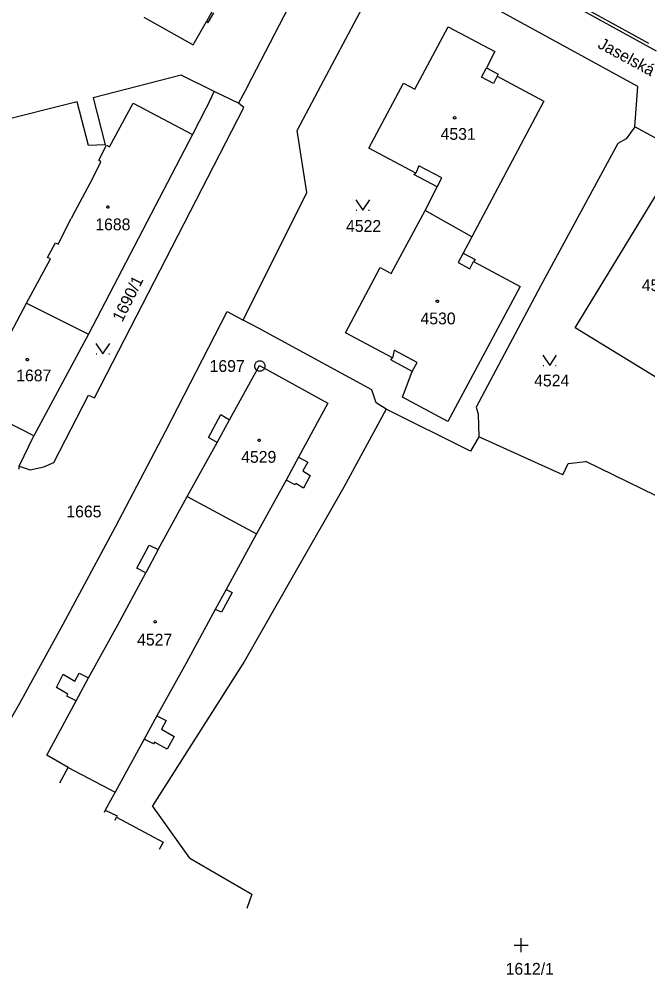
# Model space of a CAD drawing. Extents: x -528274 to -527531, y -1079304 to -1078580.
# Drawn here: x -527954.6 to -527864, y -1079223 to -1079085.4 of the extents above; entities that cross this region are included whole.
import ezdxf

# ---------------------------------------------------------------- set-up
doc = ezdxf.new("R2010")
doc.units = 0
doc.layers.add('katastrální mapa', color=7, linetype='Continuous')

msp = doc.modelspace()

# ---------------------------------------------------------------- linework, layer by layer
at = {"layer": 'katastrální mapa'}
for p, q in [((-527890.1, -1079074.91), (-527862.81, -1079089.91)), ((-527863.87, -1079088.86), (-527884.84, -1079077.28)), ((-527865.43, -1079095.09), (-527895.13, -1079078.8)), ((-527921.73, -1079095.17), (-527915.12, -1079082.34)), ((-527910.67, -1079094.17), (-527903.98, -1079081.56)), ((-527936.63, -1079085.07), (-527929.52, -1079089.06)), ((-527926.81, -1079084.3), (-527927.6, -1079085.69)), ((-527927.35, -1079085.83), (-527926.56, -1079084.44)), ((-527929.52, -1079089.06), (-527927.6, -1079085.69)), ((-527927.6, -1079085.69), (-527927.35, -1079085.83)), ((-527897.58, -1079095.45), (-527892.78, -1079086.47)), ((-527892.78, -1079086.47), (-527886.03, -1079090.03)), ((-527886.03, -1079090.03), (-527887.26, -1079092.37)), ((-527887.97, -1079093.71), (-527887.26, -1079092.37)), ((-527887.26, -1079092.37), (-527885.55, -1079093.28)), ((-527931.27, -1079093.45), (-527943.94, -1079096.7)), ((-527926.48, -1079095.78), (-527931.27, -1079093.45)), ((-527886.26, -1079094.62), (-527887.97, -1079093.71)), ((-527885.71, -1079093.59), (-527886.26, -1079094.62)), ((-527885.55, -1079093.28), (-527885.71, -1079093.59)), ((-527885.71, -1079093.59), (-527878.97, -1079097.19)), ((-527921.73, -1079095.17), (-527922.99, -1079097.47)), ((-527914.52, -1079101.41), (-527910.67, -1079094.17)), ((-527904.2, -1079103.97), (-527899.19, -1079094.59)), ((-527899.19, -1079094.59), (-527897.58, -1079095.45)), ((-527865.87, -1079100.87), (-527865.43, -1079095.09)), ((-527927.17, -1079097.21), (-527926.48, -1079095.78)), ((-527922.99, -1079097.47), (-527926.48, -1079095.78)), ((-527946.23, -1079097.26), (-527961.15, -1079101.04)), ((-527944.61, -1079103.58), (-527946.23, -1079097.26)), ((-527943.94, -1079096.7), (-527942.22, -1079103.47)), ((-527941.59, -1079103.74), (-527938.18, -1079097.48)), ((-527938.18, -1079097.48), (-527929.6, -1079101.99)), ((-527927.17, -1079097.21), (-527927.69, -1079098.23)), ((-527922.2, -1079098.11), (-527922.99, -1079097.47)), ((-527878.97, -1079097.19), (-527889.36, -1079116.7)), ((-527943.73, -1079139.94), (-527922.2, -1079098.11)), ((-527927.69, -1079098.23), (-527929.6, -1079101.99)), ((-527929.6, -1079101.99), (-527944.61, -1079130.76)), ((-527913.15, -1079110.35), (-527914.52, -1079101.41)), ((-527865.87, -1079100.87), (-527867.1, -1079102.61)), ((-527847.48, -1079111.01), (-527865.87, -1079100.87)), ((-527942.22, -1079103.47), (-527944.61, -1079103.58)), ((-527868.34, -1079103.27), (-527879.49, -1079123.84)), ((-527867.1, -1079102.61), (-527868.34, -1079103.27)), ((-527943.11, -1079105.68), (-527942.01, -1079103.52)), ((-527942.01, -1079103.52), (-527941.59, -1079103.74)), ((-527897.45, -1079107.57), (-527904.2, -1079103.97)), ((-527944, -1079108.28), (-527942.82, -1079105.92)), ((-527942.82, -1079105.92), (-527943.11, -1079105.68)), ((-527897.74, -1079107.75), (-527897.45, -1079107.57)), ((-527897.01, -1079106.5), (-527897.45, -1079107.57)), ((-527893.67, -1079108.24), (-527897.01, -1079106.5)), ((-527946.91, -1079113.74), (-527944, -1079108.28)), ((-527894.34, -1079109.52), (-527897.74, -1079107.75)), ((-527894.34, -1079109.52), (-527893.67, -1079108.24)), ((-527922.31, -1079128.71), (-527913.15, -1079110.35)), ((-527896.11, -1079112.93), (-527894.34, -1079109.52)), ((-527874.49, -1079129.82), (-527861.78, -1079109.06)), ((-527906.03, -1079112.9), (-527905.93, -1079112.9)), ((-527904.23, -1079112.9), (-527904.13, -1079112.9)), ((-527900.98, -1079122), (-527896.11, -1079112.93)), ((-527889.36, -1079116.7), (-527896.11, -1079112.93)), ((-527948.99, -1079117.76), (-527947.08, -1079114.07)), ((-527946.91, -1079113.74), (-527947.08, -1079114.07)), ((-527889.53, -1079117.02), (-527890.6, -1079119.07)), ((-527889.36, -1079116.7), (-527889.53, -1079117.02)), ((-527950.5, -1079119.68), (-527949.38, -1079117.57)), ((-527949.38, -1079117.57), (-527948.99, -1079117.76)), ((-527953.53, -1079126.27), (-527950.1, -1079119.89)), ((-527950.1, -1079119.89), (-527950.5, -1079119.68)), ((-527890.6, -1079119.07), (-527891.35, -1079120.43)), ((-527890.6, -1079119.07), (-527888.9, -1079119.98)), ((-527888.9, -1079119.98), (-527889.12, -1079120.28)), ((-527907.56, -1079130.55), (-527902.56, -1079121.16)), ((-527902.56, -1079121.16), (-527900.98, -1079122)), ((-527891.35, -1079120.43), (-527889.65, -1079121.33)), ((-527889.65, -1079121.33), (-527889.12, -1079120.28)), ((-527889.12, -1079120.28), (-527882.38, -1079123.89)), ((-527882.38, -1079123.89), (-527892.81, -1079143.32)), ((-527879.49, -1079123.84), (-527888.76, -1079141.24)), ((-527956.76, -1079132.39), (-527953.53, -1079126.27)), ((-527953.53, -1079126.27), (-527944.61, -1079130.76)), ((-527933.53, -1079144.79), (-527924.62, -1079127.48)), ((-527924.62, -1079127.48), (-527922.31, -1079128.71)), ((-527920.12, -1079129.88), (-527922.31, -1079128.71)), ((-527944.61, -1079130.76), (-527952.47, -1079145.37)), ((-527903.76, -1079138.76), (-527920.12, -1079129.88)), ((-527900.81, -1079134.15), (-527907.56, -1079130.55)), ((-527862.92, -1079136.88), (-527874.49, -1079129.82)), ((-527943.49, -1079133.57), (-527943.39, -1079133.57)), ((-527941.69, -1079133.57), (-527941.59, -1079133.57)), ((-527900.55, -1079133.03), (-527900.81, -1079134.15)), ((-527897.25, -1079134.82), (-527900.55, -1079133.03)), ((-527901.04, -1079134.45), (-527900.81, -1079134.15)), ((-527897.96, -1079136.12), (-527901.04, -1079134.45)), ((-527897.96, -1079136.12), (-527897.25, -1079134.82)), ((-527924.28, -1079143.07), (-527919.97, -1079135.24)), ((-527919.97, -1079135.24), (-527910.1, -1079140.68)), ((-527919.95, -1079135.33), (-527919.85, -1079135.33)), ((-527899.36, -1079139.8), (-527897.96, -1079136.12)), ((-527879.09, -1079135.27), (-527878.99, -1079135.27)), ((-527877.29, -1079135.27), (-527877.19, -1079135.27)), ((-527903.16, -1079140.65), (-527903.76, -1079138.76)), ((-527949.61, -1079149.23), (-527944.62, -1079139.54)), ((-527944.62, -1079139.54), (-527943.73, -1079139.94)), ((-527901.7, -1079141.56), (-527903.16, -1079140.65)), ((-527892.81, -1079143.32), (-527899.36, -1079139.8)), ((-527910.1, -1079140.68), (-527914.36, -1079148.44)), ((-527901.7, -1079141.56), (-527907.81, -1079152.78)), ((-527889.57, -1079147.62), (-527901.7, -1079141.56)), ((-527888.76, -1079141.24), (-527888.43, -1079142.25)), ((-527952.47, -1079145.37), (-527956.54, -1079143.33)), ((-527927.33, -1079145.61), (-527925.52, -1079142.33)), ((-527926.08, -1079146.35), (-527924.28, -1079143.07)), ((-527925.52, -1079142.33), (-527924.28, -1079143.07)), ((-527888.43, -1079142.25), (-527888.34, -1079145.53)), ((-527940.71, -1079158.51), (-527933.53, -1079144.79)), ((-527954.6, -1079149.75), (-527952.47, -1079145.37)), ((-527926.08, -1079146.35), (-527927.33, -1079145.61)), ((-527888.34, -1079145.53), (-527889.57, -1079147.62)), ((-527876.24, -1079151.03), (-527888.34, -1079145.53)), ((-527930.37, -1079154.15), (-527926.08, -1079146.35)), ((-527914.36, -1079148.44), (-527916.12, -1079151.76)), ((-527914.36, -1079148.44), (-527913.02, -1079149.17)), ((-527954.61, -1079150.18), (-527954.6, -1079149.75)), ((-527954.6, -1079149.75), (-527953, -1079150.31)), ((-527953, -1079150.31), (-527951.05, -1079149.86)), ((-527951.05, -1079149.86), (-527949.61, -1079149.23)), ((-527913.02, -1079149.17), (-527913.72, -1079150.44)), ((-527876.24, -1079151.03), (-527875.47, -1079149.36)), ((-527875.47, -1079149.36), (-527872.92, -1079149.09)), ((-527830.4, -1079169.97), (-527872.92, -1079149.09)), ((-527913.72, -1079150.44), (-527912.68, -1079151.1)), ((-527912.68, -1079151.1), (-527913.63, -1079152.95)), ((-527916.12, -1079151.76), (-527920.39, -1079159.49)), ((-527914.83, -1079152.45), (-527916.12, -1079151.76)), ((-527907.81, -1079152.78), (-527914.85, -1079165.13)), ((-527914.73, -1079152.28), (-527914.83, -1079152.45)), ((-527913.63, -1079152.95), (-527914.73, -1079152.28)), ((-527934.55, -1079161.78), (-527930.37, -1079154.15)), ((-527930.37, -1079154.15), (-527920.39, -1079159.49)), ((-527948.24, -1079172.53), (-527940.71, -1079158.51)), ((-527920.39, -1079159.49), (-527924.78, -1079167.53)), ((-527937.64, -1079164.44), (-527935.85, -1079161.14)), ((-527935.85, -1079161.14), (-527934.55, -1079161.78)), ((-527934.55, -1079161.78), (-527936.33, -1079165.11)), ((-527940.43, -1079172.73), (-527936.33, -1079165.11)), ((-527936.33, -1079165.11), (-527937.64, -1079164.44)), ((-527914.85, -1079165.13), (-527922.14, -1079177.83)), ((-527924.78, -1079167.53), (-527926.35, -1079170.4)), ((-527923.92, -1079167.98), (-527925.46, -1079170.79)), ((-527924.78, -1079167.53), (-527923.92, -1079167.98)), ((-527926.35, -1079170.4), (-527930.55, -1079178.12)), ((-527925.46, -1079170.79), (-527926.35, -1079170.4)), ((-527954.48, -1079183.88), (-527948.24, -1079172.53)), ((-527944.59, -1079180.27), (-527940.43, -1079172.73)), ((-527922.14, -1079177.83), (-527935.36, -1079198.69)), ((-527930.55, -1079178.12), (-527934.76, -1079185.71)), ((-527949.22, -1079181.63), (-527948.26, -1079179.71)), ((-527948.26, -1079179.71), (-527946.56, -1079180.74)), ((-527946.56, -1079180.74), (-527945.93, -1079179.58)), ((-527946.38, -1079183.58), (-527944.59, -1079180.27)), ((-527945.93, -1079179.58), (-527944.59, -1079180.27)), ((-527947.57, -1079182.59), (-527949.22, -1079181.63)), ((-527947.73, -1079182.88), (-527947.57, -1079182.59)), ((-527946.38, -1079183.58), (-527947.73, -1079182.88)), ((-527957.68, -1079189.39), (-527954.48, -1079183.88)), ((-527950.61, -1079191.38), (-527946.38, -1079183.58)), ((-527934.76, -1079185.71), (-527936.58, -1079189.07)), ((-527934.76, -1079185.71), (-527933.42, -1079186.42)), ((-527933.42, -1079186.42), (-527934.08, -1079187.65)), ((-527934.08, -1079187.65), (-527932.25, -1079188.68)), ((-527932.25, -1079188.68), (-527933.29, -1079190.51)), ((-527936.58, -1079189.07), (-527940.77, -1079196.72)), ((-527935.23, -1079189.78), (-527936.58, -1079189.07)), ((-527935.1, -1079189.54), (-527935.23, -1079189.78)), ((-527933.29, -1079190.51), (-527935.1, -1079189.54)), ((-527947.53, -1079193.18), (-527950.61, -1079191.38)), ((-527948.72, -1079195.4), (-527947.53, -1079193.18)), ((-527947.53, -1079193.18), (-527940.77, -1079196.72)), ((-527940.77, -1079196.72), (-527941.19, -1079197.49)), ((-527941.19, -1079197.49), (-527942.2, -1079199.33)), ((-527942.2, -1079199.33), (-527942.36, -1079199.67)), ((-527942.2, -1079199.33), (-527940.45, -1079200.15)), ((-527929.98, -1079206.25), (-527935.36, -1079198.69)), ((-527940.74, -1079200.76), (-527940.55, -1079200.34)), ((-527940.45, -1079200.15), (-527940.55, -1079200.34)), ((-527940.55, -1079200.34), (-527933.84, -1079203.91)), ((-527933.84, -1079203.91), (-527934.42, -1079205)), ((-527929.98, -1079206.25), (-527921.06, -1079211.4)), ((-527921.06, -1079211.4), (-527921.81, -1079213.46)), ((-527882.24, -1079219.76), (-527882.24, -1079217.76)), ((-527883.24, -1079218.76), (-527881.24, -1079218.76))]:
    msp.add_line(p, q, dxfattribs=at)
for points in [[(-527891.84, -1079099.41), (-527891.74, -1079099.43), (-527891.69, -1079099.52), (-527891.67, -1079099.58), (-527891.69, -1079099.67), (-527891.77, -1079099.74), (-527891.84, -1079099.75), (-527891.93, -1079099.72), (-527891.99, -1079099.66), (-527892.01, -1079099.58), (-527891.99, -1079099.49), (-527891.91, -1079099.42)], [(-527941.81, -1079112.26), (-527941.71, -1079112.28), (-527941.66, -1079112.37), (-527941.64, -1079112.43), (-527941.66, -1079112.52), (-527941.74, -1079112.59), (-527941.81, -1079112.6), (-527941.9, -1079112.57), (-527941.96, -1079112.51), (-527941.98, -1079112.43), (-527941.96, -1079112.34), (-527941.88, -1079112.27)], [(-527894.33, -1079125.83), (-527894.23, -1079125.85), (-527894.18, -1079125.94), (-527894.16, -1079126), (-527894.18, -1079126.09), (-527894.26, -1079126.16), (-527894.33, -1079126.17), (-527894.42, -1079126.14), (-527894.48, -1079126.08), (-527894.5, -1079126), (-527894.48, -1079125.91), (-527894.4, -1079125.84)], [(-527953.42, -1079134.24), (-527953.32, -1079134.26), (-527953.27, -1079134.35), (-527953.25, -1079134.41), (-527953.27, -1079134.5), (-527953.35, -1079134.57), (-527953.42, -1079134.58), (-527953.51, -1079134.55), (-527953.57, -1079134.49), (-527953.59, -1079134.41), (-527953.57, -1079134.32), (-527953.49, -1079134.25)], [(-527919.71, -1079134.61), (-527919.37, -1079134.8), (-527919.18, -1079135.14), (-527919.18, -1079135.53), (-527919.37, -1079135.87), (-527919.71, -1079136.06), (-527920.1, -1079136.06), (-527920.44, -1079135.87), (-527920.63, -1079135.53), (-527920.63, -1079135.14), (-527920.44, -1079134.8), (-527920.1, -1079134.61)], [(-527920.02, -1079145.87), (-527919.92, -1079145.89), (-527919.87, -1079145.98), (-527919.85, -1079146.04), (-527919.87, -1079146.13), (-527919.95, -1079146.2), (-527920.02, -1079146.21), (-527920.11, -1079146.18), (-527920.17, -1079146.12), (-527920.19, -1079146.04), (-527920.17, -1079145.95), (-527920.09, -1079145.88)], [(-527935, -1079172.01), (-527934.9, -1079172.03), (-527934.85, -1079172.12), (-527934.83, -1079172.18), (-527934.85, -1079172.27), (-527934.93, -1079172.34), (-527935, -1079172.35), (-527935.09, -1079172.32), (-527935.15, -1079172.26), (-527935.17, -1079172.18), (-527935.15, -1079172.09), (-527935.07, -1079172.02)]]:
    msp.add_lwpolyline(points, close=True, dxfattribs=at)
for points in [[(-527906.08, -1079111.4), (-527905.08, -1079112.9), (-527904.08, -1079111.4)], [(-527943.54, -1079132.07), (-527942.54, -1079133.57), (-527941.54, -1079132.07)], [(-527879.14, -1079133.77), (-527878.14, -1079135.27), (-527877.14, -1079133.77)]]:
    msp.add_lwpolyline(points, dxfattribs=at)

# ---------------------------------------------------------------- texts
for s, rotation, p in [('Jaselská', 331.5707, (-527871.35, -1079089.42)), ('1690/1', 63.4837, (-527939.74, -1079129.12))]:
    msp.add_text(s, height=1.7, rotation=rotation, dxfattribs=at).set_placement(p)
for s, p in [('4531', (-527893.86, -1079102.75)), ('1688', (-527943.62, -1079115.78)), ('4522', (-527907.49, -1079116.01)), ('4532', (-527864.87, -1079124.54)), ('4530', (-527896.76, -1079129.33)), ('1697', (-527927.15, -1079136.18)), ('1687', (-527955.02, -1079137.54)), ('4524', (-527880.38, -1079138.27)), ('4529', (-527922.6, -1079149.27)), ('1665', (-527947.8, -1079157.14)), ('4527', (-527937.6, -1079175.6)), ('1612/1', (-527884.49, -1079223.02))]:
    msp.add_text(s, height=1.7, dxfattribs=at).set_placement(p)

doc.saveas('drawing.dxf')
